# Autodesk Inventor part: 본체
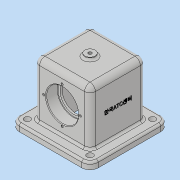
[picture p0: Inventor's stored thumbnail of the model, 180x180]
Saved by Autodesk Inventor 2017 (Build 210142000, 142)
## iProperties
Part Number: 본체
Material: 일반
Document SubType Name: Modeling
Designer: MRC
Density: 1 g/cm^3
Appearance: 기본값
Author: MRC
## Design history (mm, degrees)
sketch "스케치1"
  geometry: L1 (58, -58)-(-58, -58); L2 (-58, -58)-(-58, 58); L3 (-58, 58)-(58, 58); L4 (58, 58)-(58, -58); 3 further points
  constraints: 8 end point, 2 midpoint, 2 parallel, 1 horizontal, 1 horizontal alignment, 1 perpendicular, 1 vertical alignment
  dimensions: "d0" = 116 distance of L3.end L1.start; "d1" = 116 distance of L1.start L1.end
extrude "돌출1" new body sketch "스케치1" distance "d2" = 10; taper "d3" = 0 deg
sketch "스케치2"
  geometry: L1 (-41, 41)-(41, 41); L2 (41, 41)-(41, -41); L3 (41, -41)-(-41, -41); L4 (-41, -41)-(-41, 41); 3 further points
  constraints: 8 end point, 2 midpoint, 2 parallel, 1 horizontal, 1 horizontal alignment, 1 perpendicular, 1 vertical alignment
  dimensions: "d4" = 82 distance of L3.end L1.start; "d5" = 82 distance of L1.start L1.end
extrude "돌출2" join sketch "스케치2" distance "d6" = 80; taper "d7" = 0 deg
sketch "스케치3"
  geometry: L1 (0, 80)-(82, 80) reference; L2 (99, -10)-(-17, -10) reference; C1 r 23.5 at (41, 38); 2 further points
  constraints: 1 centre point, 1 midpoint, 1 vertical alignment
  dimensions: "d8" = 47 diameter of C1; "d9" = 48 distance from line of L2 C1.centre
extrude "돌출3" cut sketch "스케치3" distance "d10" = 17; taper "d11" = 0 deg
sketch "스케치4"
  geometry: L1 (30, 21)-(-30, 21); L2 (-30, 21)-(-30, -21); L3 (-30, -21)-(30, -21); L4 (30, -21)-(30, 21); 3 further points
  constraints: 8 end point, 2 midpoint, 2 parallel, 1 horizontal, 1 horizontal alignment, 1 perpendicular, 1 vertical alignment
  dimensions: "d12" = 42 distance of L3.end L1.start; "d13" = 60 distance of L2.end L3.end
extrude "돌출4" cut sketch "스케치4" distance "d14" = 80; taper "d15" = 0 deg
sketch "스케치6"
  geometry: C1 r 20 at (0, 0); C2 r 23.5 at (0, 0) reference; 1 further point
  constraints: 1 centre point, 1 concentric
  dimensions: "d16" = 40 diameter of C1
extrude "돌출5" cut sketch "스케치6" stored distance "d17" = 80; taper "d18" = 0 deg
node "작업 평면1"
sketch "스케치7"
  geometry: C1 r 7.5 at (0, 0); 1 further point
  constraints: 2 coincident, 1 centre point
  dimensions: "d20" = 15 diameter of C1
extrude "돌출6" join sketch "스케치7" stored distance "d21" = 80; taper "d22" = 0 deg
fillet "모깎기1" dims "d23" = 12
sketch "스케치8"
  geometry: C1 r 4.5 at (46, -46); C2 r 4.5 at (-46, -46); C3 r 4.5 at (-46, 46); C4 r 4.5 at (46, 46); A1 r 12 centre (46, -46) between (46, -58) and (58, -46) reference; A2 r 12 centre (-46, -46) between (-58, -46) and (-46, -58) reference; A3 r 12 centre (-46, 46) between (-46, 58) and (-58, 46) reference; A4 r 12 centre (46, 46) between (58, 46) and (46, 58) reference; 1 further point
  constraints: 4 centre point, 4 coincident
  dimensions: "d24" = 9 diameter of C1; "d25" = 9 diameter of C2; "d26" = 9 diameter of C3; "d27" = 9 diameter of C4
extrude "돌출7" cut sketch "스케치8" stored distance "d28" = 80; taper "d29" = 0 deg
fillet "모깎기2" dims "d30" = 3
sketch "스케치9"
  geometry: L1 (87, -10)-(-5, -10) reference; C1 r 20 at (41, 38) reference; 3 further points
  constraints: 1 midpoint, 1 vertical alignment
  dimensions: "d31" = 27 distance of C1.centre point (41, 65)
hole "구멍1" sketch "스케치9" at (41, 65) diameter "d32" = 3.242; stored, may be unused: countersink angle "d36" = 90 deg, drill point angle "d38" = 118 deg; dims "d33" = 8, "d34" = 4, "d35" = 2, "d37" = 10
sketch "스케치10"
  geometry: 1 further point
hole "구멍2" sketch "스케치10" at (0, 0) diameter "d42" = 4.917; stored, may be unused: countersink angle "d46" = 90 deg, drill point angle "d48" = 118 deg; dims "d43" = 12, "d44" = 4, "d45" = 2, "d47" = 17.1
chamfer "모따기1" distance "d49" = 1; stored, may be unused: second distance "d50" = 2, angle "d51" = 45 deg
fillet "모깎기3" dims "d52" = 3
fillet "모깎기5" dims "d54" = 8
fillet "모깎기6" dims "d55" = 3, "d56" = 8
fillet "모깎기7" dims "d57" = 0.6
fillet "모깎기8" dims "d58" = 3
fillet "모깎기9" dims "d59" = 3
sketch "스케치11"
  geometry: L1 (79, -13)-(-13, -13) reference; 3 further points
  constraints: 1 midpoint, 1 vertical alignment, 1 other
  dimensions: "d60" = 48 distance from line of L1 point (33, 35)
feature "엠보싱1" sketch "스케치11" dims "d0" = 116, "d1" = 116, "d61" = 0.5, "d62" = 0
node "솔리드1"
mirror "미러1"
pattern_circular "원형 패턴1" dims angle "d40" = 360 deg
mirror "미러2"
other parameters: "d19" = 4
